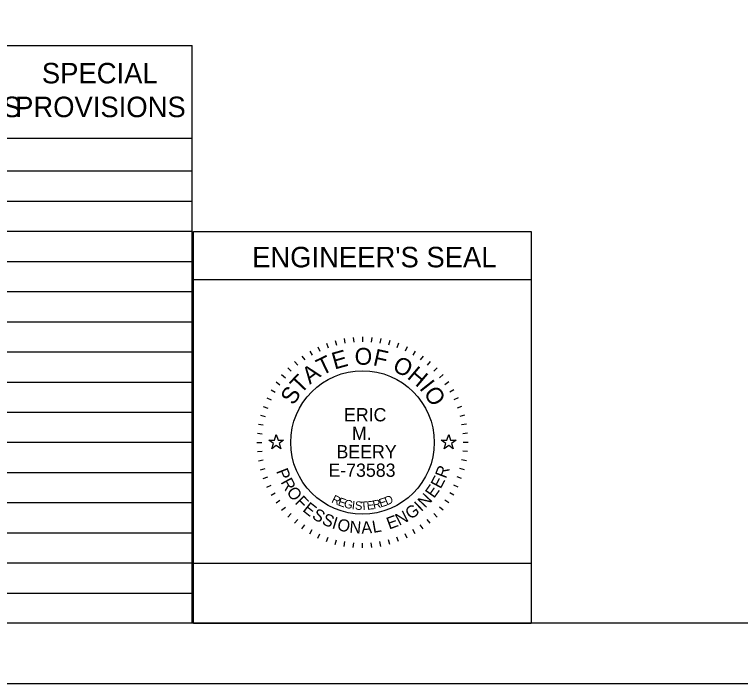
# Model space of a CAD drawing. Extents: x 0 to 82.7, y -0.2 to 22.
# Drawn here: x 22.13 to 28.15, y 0 to 5.55 of the extents above; entities that cross this region are included whole.
import ezdxf

# ---------------------------------------------------------------- set-up
doc = ezdxf.new("R2010")
doc.units = 0
for name, color, linetype in [('Default', 7, 'Continuous'), ('SH_Border', 7, 'Continuous'), ('SH_Cut_Line', 7, 'Continuous'), ('SH_Data', 7, 'Continuous'), ('SH_Text', 7, 'Continuous')]:
    doc.layers.add(name, color=color, linetype=linetype)

msp = doc.modelspace()

# ---------------------------------------------------------------- linework, layer by layer
at = {"layer": 'Default'}
for points in [[(24.2365, 2.0188), (24.2834, 2.0188), (24.2979, 2.0634), (24.3124, 2.0188), (24.3593, 2.0188), (24.3214, 1.9912), (24.3359, 1.9466), (24.2979, 1.9742), (24.2599, 1.9466), (24.2744, 1.9912)], [(25.6665, 2.0188), (25.7134, 2.0188), (25.7279, 2.0634), (25.7424, 2.0188), (25.7893, 2.0188), (25.7514, 1.9912), (25.7659, 1.9466), (25.7279, 1.9742), (25.6899, 1.9466), (25.7044, 1.9912)]]:
    msp.add_lwpolyline(points, close=True, dxfattribs=at)
at = {"layer": 'SH_Border'}
msp.add_lwpolyline([(1.5, 21.5), (33.5, 21.5), (33.5, 0.5), (1.5, 0.5)], close=True, dxfattribs=at)
at = {"layer": 'SH_Cut_Line'}
msp.add_lwpolyline([(0, 0), (34, 0), (34, 22), (0, 22)], close=True, dxfattribs=at)
at = {"layer": 'SH_Data'}
for p, q in [((10.15, 5.2917), (23.6, 5.2917)), ((23.6, 0.5), (23.6, 5.2917)), ((10.15, 4.5209), (23.6, 4.5209)), ((10.15, 4.25), (23.6, 4.25)), ((10.15, 4), (23.6, 4)), ((10.15, 3.75), (23.6, 3.75)), ((23.6129, 0.4988), (23.6129, 3.7488)), ((23.6129, 3.7488), (26.4129, 3.7488)), ((26.4129, 3.7488), (26.4129, 0.4988)), ((10.15, 3.5), (23.6, 3.5)), ((23.6129, 3.3488), (26.4129, 3.3488)), ((10.15, 3.25), (23.6, 3.25)), ((10.15, 3), (23.6, 3)), ((24.7864, 2.844), (24.7968, 2.8054)), ((24.861, 2.8605), (24.8679, 2.8211)), ((24.9366, 2.8705), (24.9401, 2.8307)), ((25.0129, 2.8738), (25.0129, 2.8338)), ((25.0892, 2.8705), (25.0857, 2.8307)), ((25.1648, 2.8605), (25.1579, 2.8211)), ((25.2394, 2.844), (25.229, 2.8054)), ((24.6431, 2.7919), (24.66, 2.7556)), ((24.7136, 2.8211), (24.7273, 2.7835)), ((25.3122, 2.8211), (25.2985, 2.7835)), ((25.3827, 2.7919), (25.3658, 2.7556)), ((10.15, 2.75), (23.6, 2.75)), ((24.511, 2.7156), (24.534, 2.6828)), ((24.5754, 2.7566), (24.5954, 2.722)), ((25.4504, 2.7566), (25.4304, 2.722)), ((25.5148, 2.7156), (25.4918, 2.6828)), ((24.4505, 2.6691), (24.4762, 2.6385)), ((25.5753, 2.6691), (25.5496, 2.6385)), ((24.3942, 2.6175), (24.4225, 2.5893)), ((25.6316, 2.6175), (25.6033, 2.5893)), ((24.3426, 2.5613), (24.3732, 2.5356)), ((25.6832, 2.5613), (25.6525, 2.5356)), ((10.15, 2.5), (23.6, 2.5)), ((24.2961, 2.5007), (24.3289, 2.4778)), ((25.7297, 2.5007), (25.6969, 2.4778)), ((24.2551, 2.4363), (24.2898, 2.4163)), ((25.7707, 2.4363), (25.736, 2.4163)), ((24.2199, 2.3686), (24.2561, 2.3517)), ((25.8059, 2.3686), (25.7697, 2.3517)), ((24.1907, 2.2981), (24.2282, 2.2844)), ((25.8351, 2.2981), (25.7975, 2.2844)), ((10.15, 2.25), (23.6, 2.25)), ((24.1677, 2.2253), (24.2063, 2.2149)), ((25.8581, 2.2253), (25.8194, 2.2149)), ((24.1512, 2.1508), (24.1906, 2.1438)), ((25.8746, 2.1508), (25.8352, 2.1438)), ((24.1412, 2.0751), (24.1811, 2.0716)), ((25.8846, 2.0751), (25.8447, 2.0716)), ((10.15, 2), (23.6, 2)), ((24.1379, 1.9988), (24.1779, 1.9988)), ((25.8879, 1.9988), (25.8479, 1.9988)), ((24.1412, 1.9226), (24.1811, 1.9261)), ((25.8846, 1.9226), (25.8447, 1.9261)), ((24.1512, 1.8469), (24.1906, 1.8538)), ((25.8746, 1.8469), (25.8352, 1.8538)), ((10.15, 1.75), (23.6, 1.75)), ((24.1677, 1.7724), (24.2063, 1.7827)), ((25.8581, 1.7724), (25.8194, 1.7827)), ((24.1907, 1.6996), (24.2282, 1.7132)), ((25.8351, 1.6996), (25.7975, 1.7132)), ((24.2199, 1.629), (24.2561, 1.6459)), ((25.8059, 1.629), (25.7697, 1.6459)), ((24.2551, 1.5613), (24.2898, 1.5813)), ((25.7707, 1.5613), (25.736, 1.5813)), ((24.2961, 1.497), (24.3289, 1.5199)), ((25.7297, 1.497), (25.6969, 1.5199)), ((10.15, 1.5), (23.6, 1.5)), ((24.3426, 1.4364), (24.3732, 1.4621)), ((25.6832, 1.4364), (25.6525, 1.4621)), ((24.3942, 1.3801), (24.4225, 1.4084)), ((25.6316, 1.3801), (25.6033, 1.4084)), ((24.4505, 1.3285), (24.4762, 1.3592)), ((25.5753, 1.3285), (25.5496, 1.3592)), ((24.511, 1.2821), (24.534, 1.3148)), ((24.5754, 1.2411), (24.5954, 1.2757)), ((25.4504, 1.2411), (25.4304, 1.2757)), ((25.5148, 1.2821), (25.4918, 1.3148)), ((10.15, 1.25), (23.6, 1.25)), ((24.6431, 1.2058), (24.66, 1.2421)), ((24.7136, 1.1766), (24.7273, 1.2142)), ((25.3122, 1.1766), (25.2985, 1.2142)), ((25.3827, 1.2058), (25.3658, 1.2421)), ((24.7864, 1.1536), (24.7968, 1.1923)), ((24.861, 1.1371), (24.8679, 1.1765)), ((24.9366, 1.1272), (24.9401, 1.167)), ((25.0129, 1.1238), (25.0129, 1.1638)), ((25.0892, 1.1272), (25.0857, 1.167)), ((25.1648, 1.1371), (25.1579, 1.1765)), ((25.2394, 1.1536), (25.229, 1.1923)), ((10.15, 1), (23.6, 1)), ((10.15, 0.75), (23.6, 0.75)), ((23.6129, 0.4988), (26.4129, 0.4988))]:
    msp.add_line(p, q, dxfattribs=at)
msp.add_lwpolyline([(23.6129, 0.4988), (23.6129, 0.9988), (26.4129, 0.9988), (26.4129, 0.4988)], close=True, dxfattribs=at)
msp.add_circle((25.0129, 1.9988), 0.595, dxfattribs=at)

# ---------------------------------------------------------------- texts
for s, height, p in [("ENGINEER'S SEAL", 0.17, (24.0975, 3.4509)), ('ERIC', 0.11, (24.8594, 2.1737)), ('M.', 0.11, (24.9255, 2.0205)), ('BEERY', 0.11, (24.7977, 1.8672)), ('E-73583', 0.11, (24.7306, 1.7139))]:
    msp.add_text(s, height=height, dxfattribs=at).set_placement(p)
for s, height, rotation, p in [('O', 0.14, 359.78119, (24.9476, 2.6431)), ('F', 0.14, 347.43619, (25.0939, 2.6406)), ('T', 0.14, 25.71674, (24.6745, 2.5507)), ('E', 0.14, 15.75706, (24.7813, 2.6026)), ('O', 0.14, 332.25863, (25.2527, 2.6003)), ('A', 0.14, 36.47472, (24.5763, 2.4769)), ('H', 0.14, 319.91363, (25.376, 2.5349)), ('T', 0.14, 46.4344, (24.5012, 2.3953)), ('I', 0.14, 308.36695, (25.4794, 2.4472)), ('S', 0.14, 57.19238, (24.441, 2.3003)), ('O', 0.14, 303.14906, (25.515, 2.4077)), ('P', 0.1, 291.49398, (24.2952, 1.7609)), ('R', 0.1, 69.23216, (25.7048, 1.6942)), ('R', 0.1, 298.73106, (24.3319, 1.6705)), ('E', 0.1, 61.99508, (25.6605, 1.6087)), ('O', 0.1, 306.46664, (24.3784, 1.5871)), ('E', 0.1, 54.75801, (25.6062, 1.5302)), ('N', 0.1, 47.02243, (25.5331, 1.4496)), ('F', 0.1, 314.7068, (24.4472, 1.4971)), ('E', 0.1, 321.43929, (24.5107, 1.4336)), ('R', 0.07, 334.48695, (24.7504, 1.5039)), ('E', 0.07, 341.03996, (24.8035, 1.4789)), ('G', 0.07, 347.47515, (24.8543, 1.4606)), ('I', 0.07, 353.78581, (24.922, 1.4456)), ('S', 0.07, 356.89262, (24.9487, 1.4417)), ('T', 0.07, 3.00609, (24.9986, 1.4375)), ('E', 0.07, 6.01169, (25.0518, 1.44)), ('R', 0.07, 11.91844, (25.1054, 1.4462)), ('E', 0.07, 17.68363, (25.1627, 1.459)), ('D', 0.07, 23.30524, (25.2139, 1.4759)), ('I', 0.1, 43.28703, (25.4997, 1.4202)), ('S', 0.1, 328.67637, (24.5872, 1.3741)), ('G', 0.1, 35.04687, (25.411, 1.3558)), ('S', 0.1, 335.91345, (24.6693, 1.3254)), ('E', 0.1, 20.07421, (25.2341, 1.2758)), ('N', 0.1, 27.31129, (25.3174, 1.3063)), ('I', 0.1, 343.15053, (24.7535, 1.2885)), ('O', 0.1, 346.88592, (24.7967, 1.274)), ('N', 0.1, 355.12608, (24.9017, 1.2506)), ('A', 0.1, 2.86166, (25.0052, 1.2425)), ('L', 0.1, 10.09874, (25.1023, 1.2479))]:
    msp.add_text(s, height=height, rotation=rotation, dxfattribs=at).set_placement(p)
at = {"layer": 'SH_Text'}
for s, p in [('SPECIAL', (22.3542, 4.9763)), ('SPECIFICATIONS', (20.2871, 4.6963)), ('PROVISIONS', (22.1323, 4.6963))]:
    msp.add_text(s, height=0.17, dxfattribs=at).set_placement(p)

doc.saveas('drawing.dxf')
